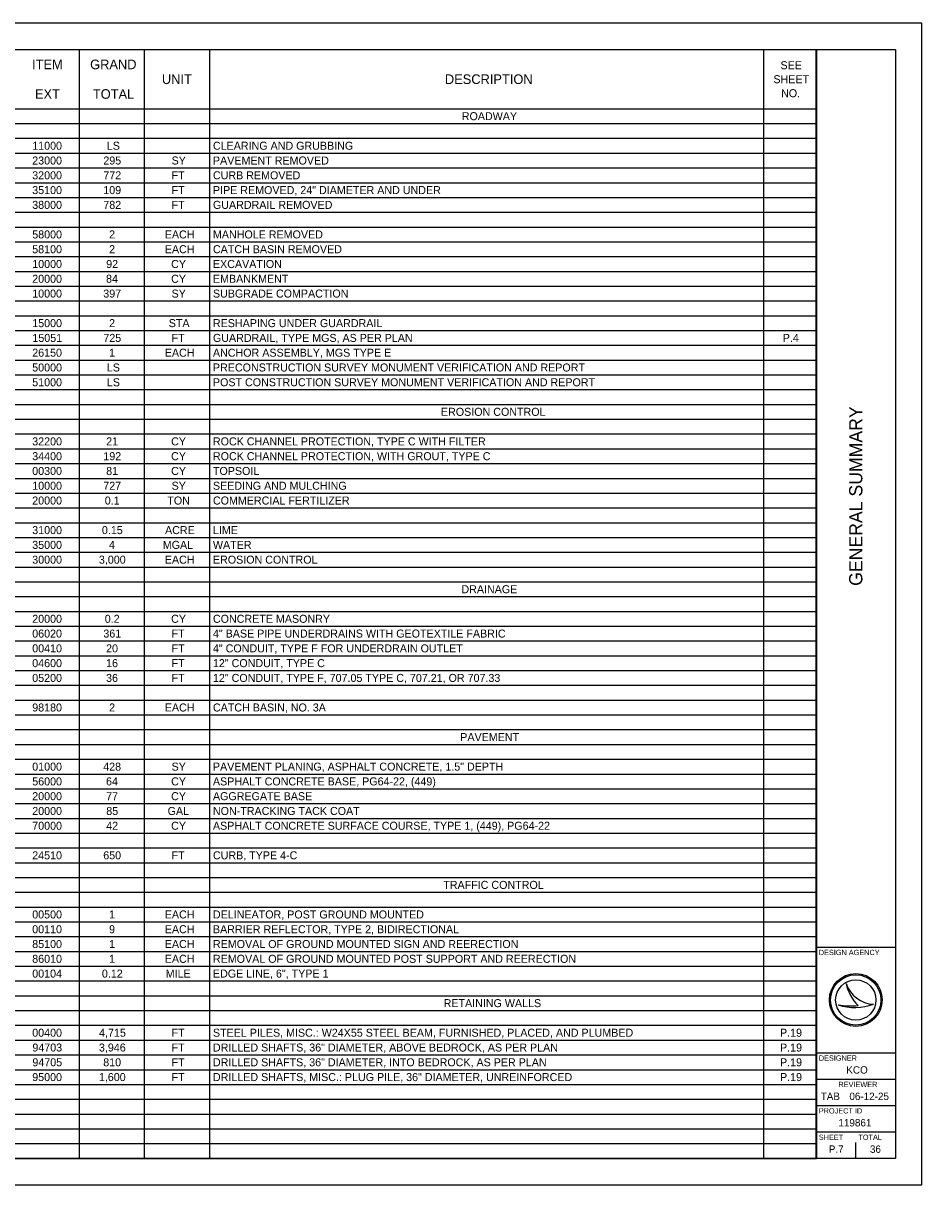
# Model space of a CAD drawing. Extents: x 0 to 34, y 0 to 22.
# Drawn here: x 16.98 to 34, y 0 to 22 of the extents above; entities that cross this region are included whole.
import ezdxf

# ---------------------------------------------------------------- set-up
doc = ezdxf.new("R2010")
doc.units = 0
for name, color, linetype in [('Default', 7, 'Continuous'), ('SH_Border', 7, 'Continuous'), ('SH_Cut_Line', 7, 'Continuous'), ('SH_Data', 7, 'Continuous')]:
    doc.layers.add(name, color=color, linetype=linetype)

msp = doc.modelspace()

# ---------------------------------------------------------------- linework, layer by layer
at = {"layer": 'Default'}
for p, q in [((1.5, 21.5), (32.004, 21.5)), ((18.036, 21.5), (18.036, 0.5)), ((19.272, 21.5), (19.272, 0.5)), ((20.507, 21.5), (20.507, 0.5)), ((30.999, 21.5), (30.999, 0.5)), ((32.004, 21.5), (32.004, 0.5)), ((1.5, 20.38), (32.004, 20.38)), ((1.5, 20.1), (32.004, 20.1)), ((1.5, 19.82), (32.004, 19.82)), ((1.5, 19.54), (32.004, 19.54)), ((1.5, 19.26), (32.004, 19.26)), ((1.5, 18.98), (32.004, 18.98)), ((1.5, 18.7), (32.004, 18.7)), ((1.5, 18.42), (32.004, 18.42)), ((1.5, 18.14), (32.004, 18.14)), ((1.5, 17.86), (32.004, 17.86)), ((1.5, 17.58), (32.004, 17.58)), ((1.5, 17.3), (32.004, 17.3)), ((1.5, 17.02), (32.004, 17.02)), ((1.5, 16.74), (32.004, 16.74)), ((1.5, 16.46), (32.004, 16.46)), ((1.5, 16.18), (32.004, 16.18)), ((1.5, 15.9), (32.004, 15.9)), ((1.5, 15.62), (32.004, 15.62)), ((1.5, 15.34), (32.004, 15.34)), ((1.5, 15.06), (32.004, 15.06)), ((1.5, 14.78), (32.004, 14.78)), ((1.5, 14.5), (32.004, 14.5)), ((1.5, 14.22), (32.004, 14.22)), ((1.5, 13.94), (32.004, 13.94)), ((1.5, 13.66), (32.004, 13.66)), ((1.5, 13.38), (32.004, 13.38)), ((1.5, 13.1), (32.004, 13.1)), ((1.5, 12.82), (32.004, 12.82)), ((1.5, 12.54), (32.004, 12.54)), ((1.5, 12.26), (32.004, 12.26)), ((1.5, 11.98), (32.004, 11.98)), ((1.5, 11.7), (32.004, 11.7)), ((1.5, 11.42), (32.004, 11.42)), ((1.5, 11.14), (32.004, 11.14)), ((1.5, 10.86), (32.004, 10.86)), ((1.5, 10.58), (32.004, 10.58)), ((1.5, 10.3), (32.004, 10.3)), ((1.5, 10.02), (32.004, 10.02)), ((1.5, 9.74), (32.004, 9.74)), ((1.5, 9.46), (32.004, 9.46)), ((1.5, 9.18), (32.004, 9.18)), ((1.5, 8.9), (32.004, 8.9)), ((1.5, 8.62), (32.004, 8.62)), ((1.5, 8.34), (32.004, 8.34)), ((1.5, 8.06), (32.004, 8.06)), ((1.5, 7.78), (32.004, 7.78)), ((1.5, 7.5), (32.004, 7.5)), ((1.5, 7.22), (32.004, 7.22)), ((1.5, 6.94), (32.004, 6.94)), ((1.5, 6.66), (32.004, 6.66)), ((1.5, 6.38), (32.004, 6.38)), ((1.5, 6.1), (32.004, 6.1)), ((1.5, 5.82), (32.004, 5.82)), ((1.5, 5.54), (32.004, 5.54)), ((1.5, 5.26), (32.004, 5.26)), ((1.5, 4.98), (32.004, 4.98)), ((1.5, 4.7), (32.004, 4.7)), ((1.5, 4.42), (32.004, 4.42)), ((1.5, 4.14), (32.004, 4.14)), ((1.5, 3.86), (32.004, 3.86)), ((1.5, 3.58), (32.004, 3.58)), ((1.5, 3.3), (32.004, 3.3)), ((1.5, 3.02), (32.004, 3.02)), ((1.5, 2.74), (32.004, 2.74)), ((1.5, 2.46), (32.004, 2.46)), ((1.5, 2.18), (32.004, 2.18)), ((1.5, 1.9), (32.004, 1.9)), ((1.5, 1.62), (32.004, 1.62)), ((1.5, 1.34), (32.004, 1.34)), ((1.5, 1.06), (32.004, 1.06)), ((1.5, 0.78), (32.004, 0.78)), ((1.5, 0.5), (32.004, 0.5))]:
    msp.add_line(p, q, dxfattribs=at)
at = {"layer": 'SH_Border'}
for p, q in [((32, 0.5), (32, 21.5)), ((32, 4.5), (33.5, 4.5)), ((32, 2.5), (33.5, 2.5)), ((32, 2), (33.5, 2)), ((32, 1.5), (33.5, 1.5)), ((32, 1), (33.5, 1))]:
    msp.add_line(p, q, dxfattribs=at)
msp.add_lwpolyline([(1.5, 21.5), (33.5, 21.5), (33.5, 0.5), (1.5, 0.5)], close=True, dxfattribs=at)
at = {"layer": 'SH_Cut_Line'}
msp.add_lwpolyline([(0, 0), (34, 0), (34, 22), (0, 22)], close=True, dxfattribs=at)
at = {"layer": 'SH_Data'}
for p, q in [((32.567, 3.81), (32.567, 3.81)), ((32.417, 3.41), (32.417, 3.41)), ((32.75, 3.5), (32.75, 3.5)), ((33.087, 3.419), (33.087, 3.419)), ((32.375, 0.675), (32.375, 0.675)), ((32.75, 0.5), (32.75, 0.8))]:
    msp.add_line(p, q, dxfattribs=at)
for radius in [0.5, 0.477, 0.477, 0.382]:
    msp.add_circle((32.75, 3.5), radius, dxfattribs=at)
for centre, radius, start, end in [((33.116, 3.998), 0.58, 198.9257, 198.9319), ((33.347, 3.97), 0.796, 191.6379, 191.6421), ((33.116, 3.998), 0.58, 198.9319, 267.1657), ((33.347, 3.97), 0.796, 191.6421, 226.0947), ((32.739, 4.37), 1.013, 251.4576, 290.0832), ((32.648, 4.654), 1.266, 259.4964, 259.4995), ((32.739, 4.37), 1.013, 251.4527, 251.4576), ((32.648, 4.654), 1.266, 259.4995, 276.6672)]:
    msp.add_arc(centre, radius, start, end, dxfattribs=at)

# ---------------------------------------------------------------- texts
at = {"layer": 'Default'}
for s, height, p in [('ITEM', 0.1818, (17.147, 21.129)), ('GRAND', 0.1818, (18.247, 21.129)), ('SEE ', 0.1515, (31.324, 21.129)), ('UNIT', 0.1818, (19.606, 20.849)), ('DESCRIPTION', 0.18184, (24.967, 20.849)), ('SHEET ', 0.1515, (31.19, 20.864)), ('EXT', 0.1818, (17.201, 20.569)), ('TOTAL', 0.1818, (18.299, 20.569)), ('NO.', 0.1515, (31.335, 20.599)), ('ROADWAY', 0.1515, (25.287, 20.164)), ('11000', 0.1515, (17.15, 19.604)), ('LS', 0.1515, (18.564, 19.604)), ('CLEARING AND GRUBBING', 0.15153, (20.573, 19.604)), ('23000', 0.1515, (17.15, 19.324)), ('295', 0.1515, (18.497, 19.324)), ('SY', 0.1515, (19.79, 19.324)), ('PAVEMENT REMOVED', 0.15153, (20.573, 19.324)), ('32000', 0.1515, (17.15, 19.044)), ('772', 0.1515, (18.497, 19.044)), ('FT', 0.1515, (19.789, 19.044)), ('CURB REMOVED', 0.15153, (20.573, 19.044)), ('35100', 0.1515, (17.15, 18.764)), ('109', 0.1515, (18.496, 18.764)), ('FT', 0.1515, (19.789, 18.764)), ('PIPE REMOVED, 24" DIAMETER AND UNDER', 0.15153, (20.573, 18.764)), ('38000', 0.1515, (17.15, 18.484)), ('782', 0.1515, (18.497, 18.484)), ('FT', 0.1515, (19.789, 18.484)), ('GUARDRAIL REMOVED', 0.15153, (20.573, 18.484)), ('58000', 0.1515, (17.15, 17.924)), ('2', 0.152, (18.606, 17.924)), ('EACH', 0.1515, (19.661, 17.924)), ('MANHOLE REMOVED', 0.15153, (20.573, 17.924)), ('58100', 0.1515, (17.15, 17.644)), ('2', 0.152, (18.606, 17.644)), ('EACH', 0.1515, (19.661, 17.644)), ('CATCH BASIN REMOVED', 0.15153, (20.573, 17.644)), ('10000', 0.1515, (17.15, 17.364)), ('92', 0.1515, (18.551, 17.364)), ('CY', 0.1515, (19.781, 17.364)), ('EXCAVATION', 0.1515, (20.573, 17.364)), ('20000', 0.1515, (17.15, 17.084)), ('84', 0.1515, (18.548, 17.084)), ('CY', 0.1515, (19.781, 17.084)), ('EMBANKMENT', 0.1515, (20.573, 17.084)), ('10000', 0.1515, (17.15, 16.804)), ('397', 0.1515, (18.496, 16.804)), ('SY', 0.1515, (19.79, 16.804)), ('SUBGRADE COMPACTION', 0.15153, (20.573, 16.804)), ('15000', 0.1515, (17.15, 16.244)), ('2', 0.152, (18.606, 16.244)), ('STA', 0.1515, (19.736, 16.244)), ('RESHAPING UNDER GUARDRAIL', 0.15153, (20.573, 16.244)), ('15051', 0.1515, (17.153, 15.964)), ('725', 0.1515, (18.497, 15.964)), ('FT', 0.1515, (19.789, 15.964)), ('GUARDRAIL, TYPE MGS, AS PER PLAN', 0.15153, (20.573, 15.964)), ('P.4', 0.1515, (31.367, 15.964)), ('26150', 0.1515, (17.15, 15.684)), ('1', 0.152, (18.606, 15.684)), ('EACH', 0.1515, (19.661, 15.684)), ('ANCHOR ASSEMBLY, MGS TYPE E', 0.15153, (20.573, 15.684)), ('50000', 0.1515, (17.15, 15.404)), ('LS', 0.1515, (18.564, 15.404)), ('PRECONSTRUCTION SURVEY MONUMENT VERIFICATION AND REPORT', 0.15153, (20.573, 15.404)), ('51000', 0.1515, (17.15, 15.124)), ('LS', 0.1515, (18.564, 15.124)), ('POST CONSTRUCTION SURVEY MONUMENT VERIFICATION AND REPORT', 0.15153, (20.573, 15.124)), ('EROSION CONTROL', 0.15153, (24.892, 14.564)), ('32200', 0.1515, (17.15, 14.004)), ('21', 0.1515, (18.551, 14.004)), ('CY', 0.1515, (19.781, 14.004)), ('ROCK CHANNEL PROTECTION, TYPE C WITH FILTER', 0.15153, (20.573, 14.004)), ('34400', 0.1515, (17.15, 13.724)), ('192', 0.1515, (18.497, 13.724)), ('CY', 0.1515, (19.781, 13.724)), ('ROCK CHANNEL PROTECTION, WITH GROUT, TYPE C', 0.15153, (20.573, 13.724)), ('00300', 0.1515, (17.15, 13.444)), ('81', 0.1515, (18.551, 13.444)), ('CY', 0.1515, (19.781, 13.444)), ('TOPSOIL', 0.1515, (20.573, 13.444)), ('10000', 0.1515, (17.15, 13.164)), ('727', 0.1515, (18.496, 13.164)), ('SY', 0.1515, (19.79, 13.164)), ('SEEDING AND MULCHING', 0.15153, (20.573, 13.164)), ('20000', 0.1515, (17.15, 12.884)), ('0.1', 0.1515, (18.524, 12.884)), ('TON', 0.1515, (19.709, 12.884)), ('COMMERCIAL FERTILIZER', 0.15153, (20.573, 12.884)), ('31000', 0.1515, (17.15, 12.324)), ('0.15', 0.1515, (18.47, 12.324)), ('ACRE', 0.1515, (19.666, 12.324)), ('LIME', 0.1515, (20.573, 12.324)), ('35000', 0.1515, (17.15, 12.044)), ('4', 0.152, (18.603, 12.044)), ('MGAL', 0.1515, (19.623, 12.044)), ('WATER', 0.1515, (20.573, 12.044)), ('30000', 0.1515, (17.15, 11.764)), ('3,000', 0.1515, (18.413, 11.764)), ('EACH', 0.1515, (19.661, 11.764)), ('EROSION CONTROL', 0.15153, (20.573, 11.764)), ('DRAINAGE', 0.1515, (25.28, 11.204)), ('20000', 0.1515, (17.15, 10.644)), ('0.2', 0.1515, (18.524, 10.644)), ('CY', 0.1515, (19.781, 10.644)), ('CONCRETE MASONRY', 0.15153, (20.573, 10.644)), ('06020', 0.1515, (17.15, 10.364)), ('361', 0.1515, (18.497, 10.364)), ('FT', 0.1515, (19.789, 10.364)), ('4" BASE PIPE UNDERDRAINS WITH GEOTEXTILE FABRIC', 0.15153, (20.573, 10.364)), ('00410', 0.1515, (17.15, 10.084)), ('20', 0.1515, (18.549, 10.084)), ('FT', 0.1515, (19.789, 10.084)), ('4" CONDUIT, TYPE F FOR UNDERDRAIN OUTLET', 0.15153, (20.573, 10.084)), ('04600', 0.1515, (17.15, 9.804)), ('16', 0.1515, (18.549, 9.804)), ('FT', 0.1515, (19.789, 9.804)), ('12" CONDUIT, TYPE C', 0.15153, (20.573, 9.804)), ('05200', 0.1515, (17.15, 9.524)), ('36', 0.1515, (18.549, 9.524)), ('FT', 0.1515, (19.789, 9.524)), ('12" CONDUIT, TYPE F, 707.05 TYPE C, 707.21, OR 707.33', 0.15153, (20.573, 9.524)), ('98180', 0.1515, (17.15, 8.964)), ('2', 0.152, (18.606, 8.964)), ('EACH', 0.1515, (19.661, 8.964)), ('CATCH BASIN, NO. 3A', 0.15153, (20.573, 8.964)), ('PAVEMENT', 0.1515, (25.258, 8.404)), ('01000', 0.1515, (17.15, 7.844)), ('428', 0.1515, (18.495, 7.844)), ('SY', 0.1515, (19.79, 7.844)), ('PAVEMENT PLANING, ASPHALT CONCRETE, 1.5" DEPTH', 0.15153, (20.573, 7.844)), ('56000', 0.1515, (17.15, 7.564)), ('64', 0.1515, (18.548, 7.564)), ('CY', 0.1515, (19.781, 7.564)), ('ASPHALT CONCRETE BASE, PG64-22, (449)', 0.15153, (20.573, 7.564)), ('20000', 0.1515, (17.15, 7.284)), ('77', 0.1515, (18.55, 7.284)), ('CY', 0.1515, (19.781, 7.284)), ('AGGREGATE BASE', 0.15153, (20.573, 7.284)), ('20000', 0.1515, (17.15, 7.004)), ('85', 0.1515, (18.552, 7.004)), ('GAL', 0.1515, (19.715, 7.004)), ('NON-TRACKING TACK COAT', 0.15153, (20.573, 7.004)), ('70000', 0.1515, (17.15, 6.724)), ('42', 0.1515, (18.551, 6.724)), ('CY', 0.1515, (19.781, 6.724)), ('ASPHALT CONCRETE SURFACE COURSE, TYPE 1, (449), PG64-22', 0.15153, (20.573, 6.724)), ('24510', 0.1515, (17.15, 6.164)), ('650', 0.1515, (18.495, 6.164)), ('FT', 0.1515, (19.789, 6.164)), ('CURB, TYPE 4-C', 0.15153, (20.573, 6.164)), ('TRAFFIC CONTROL', 0.15153, (24.936, 5.604)), ('00500', 0.1515, (17.15, 5.044)), ('1', 0.152, (18.606, 5.044)), ('EACH', 0.1515, (19.661, 5.044)), ('DELINEATOR, POST GROUND MOUNTED', 0.15153, (20.573, 5.044)), ('00110', 0.1515, (17.15, 4.764)), ('9', 0.152, (18.605, 4.764)), ('EACH', 0.1515, (19.661, 4.764)), ('BARRIER REFLECTOR, TYPE 2, BIDIRECTIONAL', 0.15153, (20.573, 4.764)), ('85100', 0.1515, (17.15, 4.484)), ('1', 0.152, (18.606, 4.484)), ('EACH', 0.1515, (19.661, 4.484)), ('REMOVAL OF GROUND MOUNTED SIGN AND REERECTION', 0.15153, (20.573, 4.484)), ('86010', 0.1515, (17.15, 4.204)), ('1', 0.152, (18.606, 4.204)), ('EACH', 0.1515, (19.661, 4.204)), ('REMOVAL OF GROUND MOUNTED POST SUPPORT AND REERECTION', 0.15153, (20.573, 4.204)), ('00104', 0.1515, (17.15, 3.924)), ('0.12', 0.1515, (18.47, 3.924)), ('MILE', 0.1515, (19.679, 3.924)), ('EDGE LINE, 6", TYPE 1', 0.15153, (20.573, 3.924)), ('RETAINING WALLS', 0.15153, (24.943, 3.364)), ('00400', 0.1515, (17.15, 2.804)), ('4,715', 0.1515, (18.416, 2.804)), ('FT', 0.1515, (19.789, 2.804)), ('STEEL PILES, MISC.: W24X55 STEEL BEAM, FURNISHED, PLACED, AND PLUMBED', 0.15153, (20.573, 2.804)), ('P.19', 0.1515, (31.315, 2.804)), ('94703', 0.1515, (17.153, 2.524)), ('3,946', 0.1515, (18.414, 2.524)), ('FT', 0.1515, (19.789, 2.524)), ('DRILLED SHAFTS, 36" DIAMETER, ABOVE BEDROCK, AS PER PLAN', 0.15153, (20.573, 2.524)), ('P.19', 0.1515, (31.315, 2.524)), ('94705', 0.1515, (17.153, 2.244)), ('810', 0.1515, (18.495, 2.244)), ('FT', 0.1515, (19.789, 2.244)), ('DRILLED SHAFTS, 36" DIAMETER, INTO BEDROCK, AS PER PLAN', 0.15153, (20.573, 2.244)), ('P.19', 0.1515, (31.315, 2.244)), ('95000', 0.1515, (17.15, 1.964)), ('1,600', 0.1515, (18.413, 1.964)), ('FT', 0.1515, (19.789, 1.964)), ('DRILLED SHAFTS, MISC.: PLUG PILE, 36" DIAMETER, UNREINFORCED', 0.15153, (20.573, 1.964)), ('P.19', 0.1515, (31.315, 1.964))]:
    msp.add_text(s, height=height, dxfattribs=at).set_placement(p)
at = {"layer": 'SH_Data'}
msp.add_text('GENERAL SUMMARY', height=0.25, rotation=90, dxfattribs=at).set_placement((32.875, 11.344))
for s, height, p in [('DESIGN AGENCY', 0.1, (32.05, 4.35)), ('DESIGNER', 0.1, (32.05, 2.35)), ('KCO', 0.14, (32.571, 2.105)), ('REVIEWER', 0.1, (32.422, 1.85)), ('TAB', 0.14, (32.086, 1.605)), ('06-12-25', 0.14, (32.629, 1.605)), ('PROJECT ID', 0.1, (32.05, 1.35)), ('119861', 0.14, (32.421, 1.105)), ('SHEET', 0.1, (32.05, 0.85)), ('TOTAL', 0.1, (32.8, 0.85)), ('P.7', 0.14, (32.239, 0.605)), ('36', 0.14, (33.018, 0.605))]:
    msp.add_text(s, height=height, dxfattribs=at).set_placement(p)

doc.saveas('drawing.dxf')
